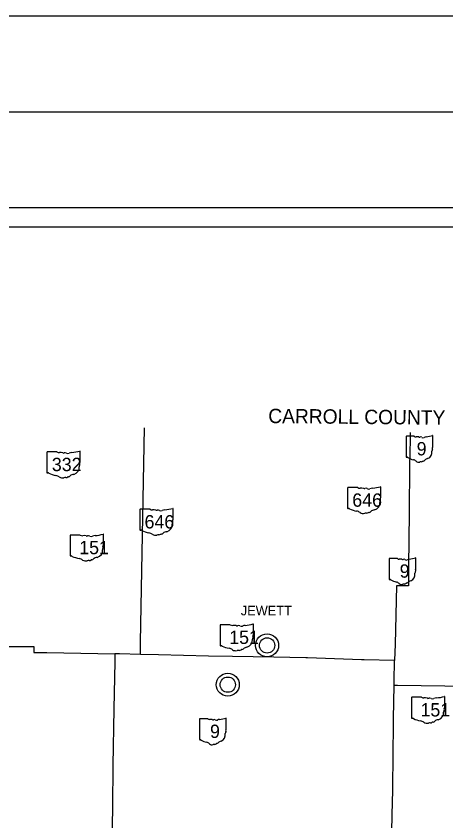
# Model space of a CAD drawing. Extents: x 0 to 34, y -32.5 to 22.
# Drawn here: x 5.387 to 7.633, y 17.798 to 22 of the extents above; entities that cross this region are included whole.
import ezdxf

# ---------------------------------------------------------------- set-up
doc = ezdxf.new("R2010")
doc.units = 0
for name, color, linetype in [('GM_X_Adjacent_County', 7, 'Continuous'), ('GM_X_County', 7, 'Continuous'), ('GM_X_County_Road', 7, 'Continuous'), ('GM_X_County_ROW', 7, 'Continuous'), ('GM_X_Minor_River', 7, 'Continuous'), ('GM_X_Minor_River_Text', 7, 'Continuous'), ('GM_X_Section', 7, 'Continuous'), ('GM_X_Township', 7, 'Continuous')]:
    doc.layers.add(name, color=color, linetype=linetype)

msp = doc.modelspace()

# ---------------------------------------------------------------- linework, layer by layer
at = {"layer": 'GM_X_Adjacent_County'}
for centre, radius in [((6.6982, 18.7143), 0.06), ((6.6982, 18.7143), 0.04), ((6.4929, 18.5093), 0.06), ((6.4929, 18.5093), 0.04)]:
    msp.add_circle(centre, radius, dxfattribs=at)
at = {"layer": 'GM_X_County'}
msp.add_lwpolyline([(1.5, 21.5), (33.5, 21.5), (33.5, 0.5), (1.5, 0.5)], close=True, dxfattribs=at)
at = {"layer": 'GM_X_County_ROW'}
for points in [[(7.446, 19.8259), (7.4449, 19.7951), (7.4435, 19.7144), (7.4429, 19.6597), (7.4398, 19.4047), (7.437, 19.1283), (7.4363, 19.0248), (7.3744, 19.026), (7.3668, 18.7212), (7.3647, 18.6359), (7.2047, 18.6388), (7.1907, 18.6392), (6.91, 18.6487), (6.9014, 18.649), (6.7335, 18.6531), (6.5182, 18.6572), (6.3921, 18.6586), (6.1309, 18.6649), (6.036, 18.6668), (6.0369, 18.7317), (6.0577, 19.8501)], [(5.3393, 18.7088), (5.4404, 18.7084), (5.4799, 18.7082), (5.4799, 18.6778), (5.548, 18.6768), (5.9032, 18.6702), (5.9029, 18.6557), (5.9024, 18.629), (5.8968, 18.3827), (5.895, 18.2837), (5.8936, 18.1857), (5.8927, 18.0879), (5.8906, 17.8717), (5.8866, 17.6728)], [(6.036, 18.6668), (5.9265, 18.6698), (5.9032, 18.6702)], [(7.3616, 18.5062), (7.3619, 18.5283), (7.3647, 18.6359)], [(7.321, 16.6465), (7.3246, 16.7856), (7.3288, 17.0035), (7.3306, 17.1648), (7.3383, 17.4444), (7.3468, 17.4448), (7.3472, 17.4976), (7.3491, 17.6075), (7.3489, 17.6422), (7.3523, 17.8326), (7.3534, 17.8901), (7.3544, 17.9622), (7.3569, 18.1501), (7.3595, 18.2961), (7.3593, 18.3312), (7.3616, 18.5062), (7.3799, 18.5062), (7.6271, 18.5029), (7.8521, 18.4984), (8.053, 18.4945), (8.318, 18.489), (8.6937, 18.4776)]]:
    msp.add_lwpolyline(points, dxfattribs=at)
at = {"layer": 'GM_X_Minor_River_Text'}
for p, q in [((7.4252, 19.8045), (7.4252, 19.6988)), ((7.4673, 19.8063), (7.4266, 19.8063)), ((7.5644, 19.7537), (7.5644, 19.8089)), ((7.5644, 19.7537), (7.5644, 19.7537)), ((5.5479, 19.7224), (5.5479, 19.6168)), ((5.6005, 19.7243), (5.5496, 19.7243)), ((5.7219, 19.6716), (5.7219, 19.7269)), ((5.7219, 19.6716), (5.7219, 19.6716)), ((7.2931, 19.4857), (7.2931, 19.541)), ((7.1191, 19.5365), (7.1191, 19.4309)), ((7.1718, 19.5384), (7.1208, 19.5384)), ((7.2931, 19.4857), (7.2931, 19.4857)), ((6.0338, 19.4232), (6.0338, 19.3176)), ((6.0865, 19.4251), (6.0356, 19.4251)), ((6.2079, 19.3724), (6.2079, 19.4277)), ((6.2078, 19.3724), (6.2079, 19.3724)), ((5.6697, 19.2888), (5.6697, 19.1832)), ((5.7224, 19.2906), (5.6715, 19.2906)), ((5.8438, 19.238), (5.8438, 19.2933)), ((5.8438, 19.238), (5.8438, 19.238)), ((7.3365, 19.1661), (7.3365, 19.0604)), ((7.3787, 19.1679), (7.3379, 19.1679)), ((7.4758, 19.1152), (7.4758, 19.1705)), ((7.4757, 19.1152), (7.4758, 19.1152)), ((6.4532, 18.82), (6.4532, 18.7143)), ((6.5058, 18.8218), (6.4549, 18.8218)), ((6.6272, 18.7692), (6.6272, 18.8244)), ((6.6272, 18.7692), (6.6272, 18.7692)), ((7.4526, 18.4414), (7.4526, 18.3357)), ((7.5053, 18.4432), (7.4543, 18.4432)), ((7.6266, 18.3905), (7.6266, 18.4458)), ((7.6266, 18.3906), (7.6266, 18.3905)), ((6.3456, 18.3291), (6.3456, 18.2234)), ((6.3878, 18.3309), (6.347, 18.3309)), ((6.4849, 18.2782), (6.4849, 18.3335)), ((6.4848, 18.2783), (6.4849, 18.2782))]:
    msp.add_line(p, q, dxfattribs=at)
for centre, radius, start, end in [((7.4268, 19.8047), 0.00161, 98.1301, 188.1301), ((7.477, 19.8186), 0.0156, 231.6195, 271.1119), ((7.4822, 19.747), 0.0562, 80.4867, 94.9883), ((7.495, 19.8053), 0.00451, 219.7921, 297.1024), ((7.5016, 19.7931), 0.00938, 54.4667, 119.1411), ((7.5137, 19.8098), 0.0113, 233.8562, 294.8282), ((7.5337, 19.774), 0.0297, 97.3462, 120.7689), ((7.5148, 19.9504), 0.1476, 275.8445, 288.9065), ((7.5629, 19.8092), 0.00155, 351.8621, 97.738), ((7.5641, 19.7496), 0.0024, 107.944, 210.337), ((7.5628, 19.7534), 0.00166, 289.6038, 7.7341), ((7.5231, 19.7235), 0.0369, 292.3089, 8.9858), ((7.57, 19.7305), 0.0105, 136.8065, 186.9296), ((7.5488, 19.7426), 0.0144, 340.033, 23.6496), ((7.4268, 19.6986), 0.00163, 171.9584, 258.3066), ((7.4271, 19.7094), 0.0124, 267.339, 280.6039), ((7.4296, 19.6927), 0.00448, 29.7484, 93.2717), ((7.4861, 19.7877), 0.1066, 240.4129, 257.1985), ((7.4543, 19.6514), 0.0334, 47.1842, 75.836), ((7.4904, 19.6922), 0.0212, 230.7004, 286.2918), ((7.5026, 19.6557), 0.0174, 85.6951, 111.2099), ((7.5042, 19.6843), 0.0113, 268.777, 315.5493), ((7.5144, 19.6741), 0.00318, 65.7517, 132.6484), ((7.513, 19.6886), 0.0119, 282.8732, 323.2771), ((7.5387, 19.6692), 0.0202, 94.4031, 142.5768), ((7.3381, 19.1663), 0.00161, 98.1301, 188.1301), ((7.3884, 19.1801), 0.0156, 231.6195, 271.1119), ((7.3936, 19.1086), 0.0562, 80.4867, 94.9883), ((7.4063, 19.1668), 0.00451, 219.7921, 297.1024), ((7.413, 19.1546), 0.00938, 54.4667, 119.1411), ((7.4251, 19.1714), 0.0113, 233.8562, 294.8282), ((7.445, 19.1356), 0.0297, 97.3462, 120.7689), ((7.4262, 19.3119), 0.1476, 275.8445, 288.9065), ((7.4742, 19.1707), 0.00155, 351.8621, 97.738), ((7.4344, 19.0851), 0.0369, 292.3089, 8.9858), ((7.4813, 19.0921), 0.0105, 136.8065, 186.9296), ((7.4754, 19.1112), 0.0024, 107.944, 210.337), ((7.4601, 19.1042), 0.0144, 340.033, 23.6496), ((7.4741, 19.115), 0.00166, 289.6038, 7.7341), ((7.3381, 19.0602), 0.00163, 171.9584, 258.3066), ((7.3384, 19.071), 0.0124, 267.339, 280.6039), ((7.3409, 19.0543), 0.00448, 29.7484, 93.2717), ((7.3975, 19.1492), 0.1066, 240.4129, 257.1985), ((7.3657, 19.0129), 0.0334, 47.1842, 75.836), ((7.4018, 19.0538), 0.0212, 230.7004, 286.2918), ((7.4155, 19.0459), 0.0113, 268.777, 315.5493), ((7.4257, 19.0356), 0.00318, 65.7517, 132.6484), ((7.4244, 19.0502), 0.0119, 282.8732, 323.2771), ((7.45, 19.0307), 0.0202, 94.4031, 142.5768), ((7.414, 19.0172), 0.0174, 85.6951, 111.2099), ((6.3472, 18.3293), 0.00161, 98.1301, 188.1301), ((6.3975, 18.3432), 0.0156, 231.6195, 271.1119), ((6.4027, 18.2716), 0.0562, 80.4867, 94.9883), ((6.4154, 18.3298), 0.00451, 219.7921, 297.1024), ((6.4221, 18.3176), 0.00938, 54.4667, 119.1411), ((6.4342, 18.3344), 0.0113, 233.8562, 294.8282), ((6.4541, 18.2986), 0.0297, 97.3462, 120.7689), ((6.4353, 18.4749), 0.1476, 275.8445, 288.9065), ((6.4833, 18.3337), 0.00155, 351.8621, 97.738), ((6.4435, 18.2481), 0.0369, 292.3089, 8.9858), ((6.4904, 18.2551), 0.0105, 136.8065, 186.9296), ((6.4845, 18.2742), 0.0024, 107.944, 210.337), ((6.4692, 18.2672), 0.0144, 340.033, 23.6496), ((6.4832, 18.278), 0.00166, 289.6038, 7.7341), ((6.3473, 18.2232), 0.00163, 171.9584, 258.3066), ((6.3475, 18.234), 0.0124, 267.339, 280.6039), ((6.35, 18.2173), 0.00448, 29.7484, 93.2717), ((6.4066, 18.3123), 0.1066, 240.4129, 257.1985), ((6.3748, 18.1759), 0.0334, 47.1842, 75.836), ((6.4109, 18.2168), 0.0212, 230.7004, 286.2918), ((6.4231, 18.1803), 0.0174, 85.6951, 111.2099), ((6.4246, 18.2089), 0.0113, 268.777, 315.5493), ((6.4348, 18.1986), 0.00318, 65.7517, 132.6484), ((6.4335, 18.2132), 0.0119, 282.8732, 323.2771), ((6.4591, 18.1937), 0.0202, 94.4031, 142.5768)]:
    msp.add_arc(centre, radius, start, end, dxfattribs=at)
for centre, major_axis, start_param, end_param in [((5.5499, 19.7227), (0.00202, 0), 1.712693, 3.28349), ((5.6127, 19.7365), (0.0196, 0), 4.042523, 4.731795), ((5.6192, 19.6649), (0.0702, 0), 1.404758, 1.657858), ((5.6351, 19.7232), (0.00564, 0), 3.836095, 5.185415), ((5.6434, 19.711), (0.0117, 0), 0.950623, 2.079405), ((5.6585, 19.7277), (0.0141, 0), 4.081561, 5.145723), ((5.6834, 19.692), (0.0371, 0), 1.699011, 2.107814), ((5.6599, 19.8683), (0.1845, 0), 4.814394, 5.042369), ((5.72, 19.7271), (0.00194, 0), 6.141152, 7.989035), ((5.7214, 19.6675), (0.003, 0), 1.883978, 3.671073), ((5.7024, 19.6606), (0.018, 0), 5.934695, 6.695948), ((5.7198, 19.6714), (0.00207, 0), 5.05454, 6.418171), ((5.6702, 19.6414), (0.0462, 0), 5.101752, 6.440018), ((5.7288, 19.6485), (0.0131, 0), 2.387724, 3.262537), ((5.5499, 19.6165), (0.00203, 0), 3.00124, 4.508301), ((5.5502, 19.6274), (0.0155, 0), 4.665946, 4.897461), ((5.5534, 19.6107), (0.0056, 0), 0.519207, 1.627899), ((5.624, 19.7056), (0.1333, 0), 4.195997, 4.488961), ((5.5843, 19.5693), (0.0417, 0), 0.823519, 1.323587), ((5.6294, 19.6102), (0.0265, 0), 4.026481, 4.996735), ((5.6447, 19.5736), (0.0217, 0), 1.495662, 1.94098), ((5.6466, 19.6022), (0.0141, 0), 4.691044, 5.507374), ((5.6594, 19.592), (0.00397, 0), 1.147584, 2.315152), ((5.6577, 19.6065), (0.0149, 0), 4.937069, 5.64225), ((5.6897, 19.5871), (0.0253, 0), 1.647645, 2.488434), ((7.2311, 19.6824), (0.1845, 0), 4.814394, 5.042369), ((7.2912, 19.5412), (0.00194, 0), 6.141152, 7.989035), ((7.1211, 19.5368), (0.00202, 0), 1.712693, 3.28349), ((7.1839, 19.5506), (0.0196, 0), 4.042523, 4.731795), ((7.1904, 19.479), (0.0702, 0), 1.404758, 1.657858), ((7.2063, 19.5373), (0.00564, 0), 3.836095, 5.185415), ((7.2146, 19.5251), (0.0117, 0), 0.950623, 2.079405), ((7.2298, 19.5418), (0.0141, 0), 4.081561, 5.145723), ((7.2547, 19.5061), (0.0371, 0), 1.699011, 2.107814), ((7.2415, 19.4555), (0.0462, 0), 5.101752, 6.440018), ((7.3001, 19.4626), (0.0131, 0), 2.387724, 3.262537), ((7.2927, 19.4816), (0.003, 0), 1.883978, 3.671073), ((7.2736, 19.4747), (0.018, 0), 5.934695, 6.695948), ((7.2911, 19.4855), (0.00207, 0), 5.05454, 6.418171), ((6.0358, 19.4235), (0.00202, 0), 1.712693, 3.28349), ((6.0987, 19.4373), (0.0196, 0), 4.042523, 4.731795), ((6.1051, 19.3657), (0.0702, 0), 1.404758, 1.657858), ((6.1211, 19.424), (0.00564, 0), 3.836095, 5.185415), ((6.1294, 19.4118), (0.0117, 0), 0.950623, 2.079405), ((6.1445, 19.4285), (0.0141, 0), 4.081561, 5.145723), ((6.1694, 19.3928), (0.0371, 0), 1.699011, 2.107814), ((6.1459, 19.5691), (0.1845, 0), 4.814394, 5.042369), ((6.2059, 19.4279), (0.00194, 0), 6.141152, 7.989035), ((7.1211, 19.4306), (0.00203, 0), 3.00124, 4.508301), ((7.1214, 19.4415), (0.0155, 0), 4.665946, 4.897461), ((7.1246, 19.4248), (0.0056, 0), 0.519207, 1.627899), ((7.1953, 19.5197), (0.1333, 0), 4.195997, 4.488961), ((7.1555, 19.3834), (0.0417, 0), 0.823519, 1.323587), ((7.2289, 19.4206), (0.0149, 0), 4.937069, 5.64225), ((7.2609, 19.4012), (0.0253, 0), 1.647645, 2.488434), ((6.2058, 19.3722), (0.00207, 0), 5.05454, 6.418171), ((7.2006, 19.4243), (0.0265, 0), 4.026481, 4.996735), ((7.2159, 19.3877), (0.0217, 0), 1.495662, 1.94098), ((7.2178, 19.4163), (0.0141, 0), 4.691044, 5.507374), ((7.2306, 19.4061), (0.00397, 0), 1.147584, 2.315152), ((6.1562, 19.3422), (0.0462, 0), 5.101752, 6.440018), ((6.2148, 19.3493), (0.0131, 0), 2.387724, 3.262537), ((6.2074, 19.3683), (0.003, 0), 1.883978, 3.671073), ((6.1883, 19.3614), (0.018, 0), 5.934695, 6.695948), ((5.6717, 19.289), (0.00202, 0), 1.712693, 3.28349), ((5.7346, 19.3029), (0.0196, 0), 4.042523, 4.731795), ((5.741, 19.2313), (0.0702, 0), 1.404758, 1.657858), ((5.7653, 19.2774), (0.0117, 0), 0.950623, 2.079405), ((5.8053, 19.2584), (0.0371, 0), 1.699011, 2.107814), ((5.7818, 19.4347), (0.1845, 0), 4.814394, 5.042369), ((5.8418, 19.2935), (0.00194, 0), 6.141152, 7.989035), ((6.0359, 19.3173), (0.00203, 0), 3.00124, 4.508301), ((6.0362, 19.3282), (0.0155, 0), 4.665946, 4.897461), ((6.0393, 19.3115), (0.0056, 0), 0.519207, 1.627899), ((6.11, 19.4064), (0.1333, 0), 4.195997, 4.488961), ((6.0703, 19.2701), (0.0417, 0), 0.823519, 1.323587), ((6.1154, 19.311), (0.0265, 0), 4.026481, 4.996735), ((6.1307, 19.2744), (0.0217, 0), 1.495662, 1.94098), ((6.1326, 19.303), (0.0141, 0), 4.691044, 5.507374), ((6.1453, 19.2928), (0.00397, 0), 1.147584, 2.315152), ((6.1436, 19.3073), (0.0149, 0), 4.937069, 5.64225), ((6.1757, 19.2879), (0.0253, 0), 1.647645, 2.488434), ((5.757, 19.2896), (0.00564, 0), 3.836095, 5.185415), ((5.7804, 19.2941), (0.0141, 0), 4.081561, 5.145723), ((5.7921, 19.2078), (0.0462, 0), 5.101752, 6.440018), ((5.8507, 19.2148), (0.0131, 0), 2.387724, 3.262537), ((5.8433, 19.2339), (0.003, 0), 1.883978, 3.671073), ((5.8242, 19.2269), (0.018, 0), 5.934695, 6.695948), ((5.8417, 19.2378), (0.00207, 0), 5.05454, 6.418171), ((5.6718, 19.1829), (0.00203, 0), 3.00124, 4.508301), ((5.6721, 19.1937), (0.0155, 0), 4.665946, 4.897461), ((5.6752, 19.1771), (0.0056, 0), 0.519207, 1.627899), ((5.7459, 19.272), (0.1333, 0), 4.195997, 4.488961), ((5.7062, 19.1357), (0.0417, 0), 0.823519, 1.323587), ((5.7812, 19.1584), (0.00397, 0), 1.147584, 2.315152), ((5.7795, 19.1729), (0.0149, 0), 4.937069, 5.64225), ((5.8116, 19.1535), (0.0253, 0), 1.647645, 2.488434), ((5.7513, 19.1765), (0.0265, 0), 4.026481, 4.996735), ((5.7666, 19.14), (0.0217, 0), 1.495662, 1.94098), ((5.7685, 19.1686), (0.0141, 0), 4.691044, 5.507374), ((6.5652, 18.9659), (0.1845, 0), 4.814394, 5.042369), ((6.6253, 18.8247), (0.00194, 0), 6.141152, 7.989035), ((6.4552, 18.8202), (0.00202, 0), 1.712693, 3.28349), ((6.518, 18.8341), (0.0196, 0), 4.042523, 4.731795), ((6.5245, 18.7625), (0.0702, 0), 1.404758, 1.657858), ((6.5404, 18.8208), (0.00564, 0), 3.836095, 5.185415), ((6.5487, 18.8086), (0.0117, 0), 0.950623, 2.079405), ((6.5638, 18.8253), (0.0141, 0), 4.081561, 5.145723), ((6.5887, 18.7895), (0.0371, 0), 1.699011, 2.107814), ((6.5755, 18.739), (0.0462, 0), 5.101752, 6.440018), ((6.6341, 18.746), (0.0131, 0), 2.387724, 3.262537), ((6.6267, 18.7651), (0.003, 0), 1.883978, 3.671073), ((6.6077, 18.7581), (0.018, 0), 5.934695, 6.695948), ((6.6251, 18.7689), (0.00207, 0), 5.05454, 6.418171), ((6.4552, 18.7141), (0.00203, 0), 3.00124, 4.508301), ((6.4555, 18.7249), (0.0155, 0), 4.665946, 4.897461), ((6.4587, 18.7082), (0.0056, 0), 0.519207, 1.627899), ((6.5293, 18.8032), (0.1333, 0), 4.195997, 4.488961), ((6.4896, 18.6669), (0.0417, 0), 0.823519, 1.323587), ((6.595, 18.6847), (0.0253, 0), 1.647645, 2.488434), ((6.5347, 18.7077), (0.0265, 0), 4.026481, 4.996735), ((6.55, 18.6712), (0.0217, 0), 1.495662, 1.94098), ((6.5519, 18.6998), (0.0141, 0), 4.691044, 5.507374), ((6.5647, 18.6896), (0.00397, 0), 1.147584, 2.315152), ((6.563, 18.7041), (0.0149, 0), 4.937069, 5.64225), ((7.5647, 18.5873), (0.1845, 0), 4.814394, 5.042369), ((7.6247, 18.446), (0.00194, 0), 6.141152, 7.989035), ((7.4546, 18.4416), (0.00202, 0), 1.712693, 3.28349), ((7.5174, 18.4555), (0.0196, 0), 4.042523, 4.731795), ((7.5239, 18.3839), (0.0702, 0), 1.404758, 1.657858), ((7.5399, 18.4422), (0.00564, 0), 3.836095, 5.185415), ((7.5481, 18.4299), (0.0117, 0), 0.950623, 2.079405), ((7.5633, 18.4467), (0.0141, 0), 4.081561, 5.145723), ((7.5882, 18.4109), (0.0371, 0), 1.699011, 2.107814), ((7.575, 18.3604), (0.0462, 0), 5.101752, 6.440018), ((7.6336, 18.3674), (0.0131, 0), 2.387724, 3.262537), ((7.6262, 18.3865), (0.003, 0), 1.883978, 3.671073), ((7.6071, 18.3795), (0.018, 0), 5.934695, 6.695948), ((7.6246, 18.3903), (0.00207, 0), 5.05454, 6.418171), ((7.4546, 18.3355), (0.00203, 0), 3.00124, 4.508301), ((7.4549, 18.3463), (0.0155, 0), 4.665946, 4.897461), ((7.4581, 18.3296), (0.0056, 0), 0.519207, 1.627899), ((7.5288, 18.4246), (0.1333, 0), 4.195997, 4.488961), ((7.5945, 18.306), (0.0253, 0), 1.647645, 2.488434), ((7.489, 18.2882), (0.0417, 0), 0.823519, 1.323587), ((7.5341, 18.3291), (0.0265, 0), 4.026481, 4.996735), ((7.5494, 18.2926), (0.0217, 0), 1.495662, 1.94098), ((7.5514, 18.3212), (0.0141, 0), 4.691044, 5.507374), ((7.5641, 18.3109), (0.00397, 0), 1.147584, 2.315152), ((7.5624, 18.3255), (0.0149, 0), 4.937069, 5.64225)]:
    msp.add_ellipse(centre, major_axis=major_axis, ratio=0.8, start_param=start_param, end_param=end_param, dxfattribs=at)
at = {"layer": 'GM_X_Section'}
msp.add_lwpolyline([(0, 0), (34, 0), (34, 22), (0, 22)], close=True, dxfattribs=at)
at = {"layer": 'GM_X_Township'}
for p, q in [((2, 21), (9, 21)), ((2.1, 20.9), (8.9, 20.9))]:
    msp.add_line(p, q, dxfattribs=at)

# ---------------------------------------------------------------- texts
at = {"layer": 'GM_X_County_Road'}
msp.add_text('JEWETT', height=0.05, rotation=0, dxfattribs=at).set_placement((6.5606, 18.8711))
at = {"layer": 'GM_X_Minor_River'}
msp.add_text('CARROLL COUNTY', height=0.075, rotation=359.4336, dxfattribs=at).set_placement((6.7041, 19.8752))
at = {"layer": 'GM_X_Minor_River_Text'}
for s, height, p in [('9', 0.0696, (7.4796, 19.7063)), ('332', 0.06961, (5.5736, 19.6242)), ('646', 0.06961, (7.1432, 19.4383)), ('646', 0.06961, (6.0579, 19.325)), ('151', 0.06961, (5.7167, 19.1906)), ('9', 0.0696, (7.3909, 19.0678)), ('151', 0.06961, (6.5001, 18.7218)), ('151', 0.06961, (7.4996, 18.3432)), ('9', 0.0696, (6.4, 18.2309))]:
    msp.add_text(s, height=height, dxfattribs=at).set_placement(p)

doc.saveas('drawing.dxf')
